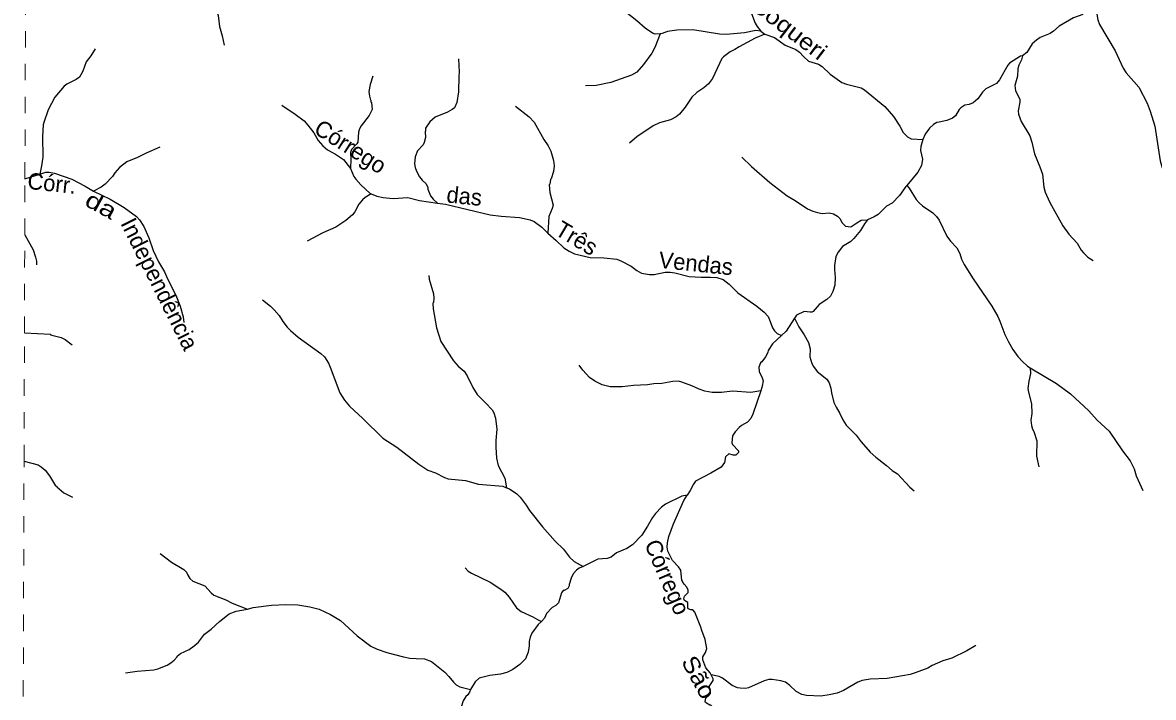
# Model space of a CAD drawing. Extents: x 551.6 to 577.6, y 7567 to 7594.7.
# Drawn here: x 551.65 to 558.55, y 7579.74 to 7583.85 of the extents above; entities that cross this region are included whole.
import ezdxf
from ezdxf.enums import TextEntityAlignment as Align

# ---------------------------------------------------------------- set-up
doc = ezdxf.new("R2010")
doc.units = 0
doc.header["$LTSCALE"] = 0.04
doc.linetypes.add('SHORT_DASHED', pattern=[2.7, 1.5, -1.2])
doc.layers.add('53', color=7, linetype='SHORT_DASHED', lineweight=13)
doc.layers.add('7', color=7, linetype='Continuous', lineweight=25)
doc.layers.add('61', color=7, linetype='Continuous')

msp = doc.modelspace()

# ---------------------------------------------------------------- linework, layer by layer
at = {"layer": '53'}
msp.add_lwpolyline([(551.6503, 7578.541), (551.6589, 7581.176), (551.6615, 7581.9586), (551.6634, 7582.5573), (551.6645, 7582.8996), (551.6852, 7589.2613), (551.6863, 7589.5882), (551.6896, 7590.6141), (551.6917, 7591.2598), (551.6958, 7592.5139), (551.6971, 7592.9033), (551.701, 7594.113), (551.703, 7594.7296), (552.7903, 7594.7256), (553.4424, 7594.7233), (554.6279, 7594.7189), (556.5859, 7594.7118), (557.3702, 7594.7089), (557.7663, 7594.7075), (559.9893, 7594.6994)], dxfattribs=at)
at = {"layer": '7'}
msp.add_line((551.6645, 7582.8996), (551.7544, 7582.9273), dxfattribs=at)
for points in [[(552.7391, 7584.4841), (552.7273, 7584.4326), (552.7273, 7584.3988), (552.7337, 7584.3763), (552.7466, 7584.3529), (552.7804, 7584.3232), (552.7933, 7584.2958), (552.7933, 7584.2507), (552.7691, 7584.1493), (552.7667, 7584.0962), (552.7836, 7584.0286), (552.7933, 7584.0061), (552.8222, 7583.9626), (552.8448, 7583.895), (552.8528, 7583.8274), (552.8689, 7583.7711), (552.8802, 7583.7139)], [(556.0535, 7584.2708), (556.0607, 7584.2547), (556.0656, 7584.1622), (556.0624, 7584.0761), (556.0591, 7584.0688), (556.064, 7584.0286), (556.0865, 7583.9739), (556.0897, 7583.9449), (556.0994, 7583.9063), (556.1211, 7583.8483), (556.134, 7583.8266), (556.1565, 7583.7992), (556.1801, 7583.78)], [(555.5411, 7583.7827), (555.5119, 7583.7815), (555.4942, 7583.7871), (555.4507, 7583.8169), (555.4, 7583.8628), (555.2455, 7583.9843), (555.2366, 7583.9948), (555.2238, 7584.0286), (555.2238, 7584.1187)], [(558.1211, 7583.8998), (558.0639, 7583.8813), (557.9778, 7583.829), (557.9424, 7583.7984), (557.9215, 7583.7847), (557.8619, 7583.7606), (557.8386, 7583.7445), (557.8128, 7583.7212), (557.779, 7583.6696), (557.7527, 7583.6485)], [(558.204, 7583.9281), (558.2128, 7583.8692), (558.224, 7583.8403), (558.319, 7583.6793), (558.3681, 7583.5731), (558.3858, 7583.5449), (558.4631, 7583.4572), (558.5138, 7583.3606), (558.5331, 7583.3123), (558.5613, 7583.2206), (558.5943, 7583.0081), (558.6063, 7582.9663), (558.6192, 7582.9373)], [(556.1565, 7583.7992), (556.1251, 7583.8024), (556.0559, 7583.7887), (555.9449, 7583.7783), (555.9046, 7583.7807), (555.7405, 7583.8081), (555.6439, 7583.8048), (555.5875, 7583.7968), (555.5537, 7583.7839), (555.5411, 7583.7827)], [(555.5411, 7583.7827), (555.5087, 7583.6986), (555.4909, 7583.6648), (555.4402, 7583.5956), (555.3984, 7583.5489), (555.367, 7583.5312), (555.2415, 7583.4869), (555.1513, 7583.4676), (555.0861, 7583.4652)], [(556.1801, 7583.78), (556.1211, 7583.7557), (556.0237, 7583.7042), (555.998, 7583.6873), (555.9682, 7583.6737), (555.9279, 7583.6423), (555.9191, 7583.6326), (555.8603, 7583.5111), (555.8362, 7583.4789), (555.8081, 7583.4531), (555.7654, 7583.4242), (555.7356, 7583.3968), (555.6954, 7583.3365), (555.66, 7583.2938), (555.639, 7583.2777), (555.6052, 7583.2592), (555.5376, 7583.2399), (555.499, 7583.2214), (555.3992, 7583.1538), (555.3549, 7583.1168)], [(556.1801, 7583.78), (556.2402, 7583.7598), (556.3054, 7583.7139), (556.369, 7583.6873), (556.3923, 7583.6705), (556.4173, 7583.6455)], [(552.0931, 7583.6914), (552.0665, 7583.6479), (552.0384, 7583.6117), (552.0174, 7583.5554), (551.9965, 7583.5191), (551.9764, 7583.5046), (551.9201, 7583.4765), (551.9031, 7583.4636), (551.8468, 7583.3976), (551.8066, 7583.3196), (551.7792, 7583.2431), (551.776, 7583.227), (551.7712, 7583.1562), (551.7728, 7583.0306), (551.7663, 7582.9775), (551.7544, 7582.9273)], [(554.3111, 7583.6302), (554.3159, 7583.5489), (554.3127, 7583.5248), (554.3103, 7583.4282), (554.3015, 7583.3638), (554.287, 7583.3324), (554.2725, 7583.3212), (554.2435, 7583.3059), (554.1679, 7583.2745), (554.1349, 7583.2471), (554.1099, 7583.2085), (554.1099, 7583.1916), (554.1067, 7583.186), (554.1099, 7583.1498), (554.1019, 7583.1192), (554.0946, 7583.1063), (554.0616, 7583.0693), (554.0455, 7583.0331), (554.0423, 7582.9904), (554.0455, 7582.9679), (554.0536, 7582.9453), (554.0721, 7582.9115), (554.0882, 7582.8906), (554.1139, 7582.8673), (554.1244, 7582.8455)], [(556.4173, 7583.6455), (556.4471, 7583.6157), (556.5074, 7583.5972), (556.53, 7583.5843), (556.5791, 7583.5368), (556.6499, 7583.4861), (556.6788, 7583.4757), (556.7682, 7583.4539), (556.7883, 7583.4411), (556.913, 7583.3389), (556.9653, 7583.2793), (557.0056, 7583.219), (557.0257, 7583.1819), (557.0523, 7583.1554), (557.074, 7583.1425), (557.1448, 7583.1388)], [(557.7527, 7583.6485), (557.7404, 7583.6471), (557.6736, 7583.6045), (557.6631, 7583.5924), (557.614, 7583.5023), (557.5947, 7583.4797), (557.5303, 7583.4467), (557.5102, 7583.4274), (557.4804, 7583.3871), (557.4523, 7583.3622), (557.4273, 7583.3525), (557.4016, 7583.3477), (557.3774, 7583.3324), (557.3677, 7583.322), (557.3452, 7583.2825), (557.3259, 7583.268), (557.2921, 7583.2543), (557.2438, 7583.2447)], [(557.7527, 7583.6485), (557.7476, 7583.6246), (557.7315, 7583.5908), (557.7251, 7583.5699), (557.7235, 7583.5248), (557.7074, 7583.4685), (557.7106, 7583.4347), (557.7363, 7583.3847), (557.7363, 7583.367), (557.7267, 7583.3139), (557.7283, 7583.293), (557.746, 7583.2479), (557.7975, 7583.161), (557.8104, 7583.1224), (557.8257, 7583.0516), (557.8595, 7582.9727), (557.8748, 7582.9276), (557.8844, 7582.8471), (557.8917, 7582.8182), (557.9005, 7582.7989)], [(553.7872, 7583.5256), (553.7719, 7583.4749), (553.7638, 7583.4314), (553.7671, 7583.4025), (553.7735, 7583.3791), (553.7767, 7583.3775), (553.7767, 7583.367), (553.7807, 7583.3638), (553.784, 7583.322), (553.7646, 7583.2858), (553.7164, 7583.2222), (553.7059, 7583.2029), (553.6995, 7583.1836), (553.6954, 7583.1224), (553.6898, 7583.1111), (553.6576, 7583.0781), (553.6514, 7583.0591), (553.6536, 7583.0182), (553.6512, 7582.9613)], [(553.2335, 7583.3485), (553.3148, 7583.293), (553.3679, 7583.252), (553.392, 7583.2262), (553.4282, 7583.1787), (553.454, 7583.132), (553.483, 7583.0998), (553.5119, 7583.0765), (553.5611, 7583.0491), (553.6085, 7583.0169), (553.6512, 7582.9613)], [(554.6596, 7583.3421), (554.7417, 7583.2777), (554.7731, 7583.2447), (554.8326, 7583.1385), (554.8576, 7583.0999), (554.8737, 7583.0677), (554.8906, 7583.0113), (554.8954, 7582.9775), (554.8914, 7582.9437), (554.8761, 7582.8995), (554.8721, 7582.8954), (554.868, 7582.8665), (554.8648, 7582.8616), (554.868, 7582.815), (554.8882, 7582.7377), (554.8833, 7582.7168), (554.8632, 7582.6685), (554.8571, 7582.5664)], [(557.2438, 7583.2447), (557.2309, 7583.2415), (557.21, 7583.2302), (557.1867, 7583.2085), (557.1601, 7583.1707), (557.1448, 7583.1388)], [(557.1448, 7583.1388), (557.1327, 7583.0966), (557.1311, 7583.0709), (557.1432, 7583.0194), (557.136, 7582.9807), (557.115, 7582.9397), (557.0477, 7582.8573)], [(552.4883, 7583.091), (552.4045, 7583.0548), (552.3522, 7583.0282), (552.2862, 7583.0025), (552.2412, 7582.967), (552.2138, 7582.9357), (552.1985, 7582.9131), (552.1551, 7582.8656), (552.1301, 7582.8479), (552.0826, 7582.8242)], [(556.0406, 7583.0298), (556.0986, 7582.9735), (556.2112, 7582.8753), (556.3167, 7582.7948), (556.3666, 7582.7658), (556.4406, 7582.716), (556.4728, 7582.7007), (556.5018, 7582.6926), (556.5308, 7582.6878), (556.5742, 7582.691), (556.6, 7582.6846), (556.6241, 7582.6709), (556.6402, 7582.6556), (556.6498, 7582.6322), (556.674, 7582.6097), (556.7046, 7582.6057), (556.7424, 7582.6306)], [(551.7544, 7582.9273), (551.7921, 7582.9389), (551.8114, 7582.9389), (551.8452, 7582.9332), (551.9498, 7582.8962), (552.0319, 7582.8544), (552.0826, 7582.8242)], [(553.6512, 7582.9613), (553.6729, 7582.9131), (553.685, 7582.897), (553.7155, 7582.8616), (553.7719, 7582.8101), (553.7783, 7582.8074)], [(554.1244, 7582.8455), (554.1244, 7582.8359), (554.1405, 7582.7956), (554.1558, 7582.7755), (554.1832, 7582.7497)], [(557.0477, 7582.8573), (557.041, 7582.8528), (557.0032, 7582.7972), (556.9589, 7582.7506), (556.9235, 7582.732), (556.872, 7582.6805), (556.8479, 7582.666), (556.8079, 7582.6495)], [(557.0477, 7582.8573), (557.0611, 7582.8423), (557.1046, 7582.7723), (557.1223, 7582.753), (557.144, 7582.7337), (557.2052, 7582.691), (557.2293, 7582.6693), (557.2454, 7582.6476), (557.2921, 7582.5494), (557.3146, 7582.5188), (557.3524, 7582.4769), (557.3701, 7582.4431), (557.3814, 7582.4093), (557.3975, 7582.3771), (557.4514, 7582.2886), (557.5657, 7582.1212), (557.6019, 7582.0601), (557.6156, 7582.0311), (557.6454, 7581.949), (557.6671, 7581.9039), (557.6945, 7581.8589), (557.7259, 7581.8154)], [(552.0826, 7582.8242), (552.184, 7582.7739), (552.2693, 7582.7248), (552.3458, 7582.6693), (552.3635, 7582.6492), (552.3908, 7582.6089), (552.4206, 7582.5397), (552.4472, 7582.4608), (552.4794, 7582.3932), (552.5164, 7582.3321), (552.5293, 7582.3031)], [(553.7783, 7582.8074), (553.7421, 7582.7852), (553.7244, 7582.7699), (553.7035, 7582.7449), (553.6777, 7582.6974), (553.6633, 7582.6789), (553.6238, 7582.6443), (553.5627, 7582.6049), (553.4822, 7582.5703), (553.388, 7582.518)], [(553.7783, 7582.8074), (553.8122, 7582.7932), (553.8508, 7582.7844), (553.9119, 7582.7795), (554.0013, 7582.7844)], [(554.0013, 7582.7844), (554.0729, 7582.7666), (554.1832, 7582.7497)], [(557.9005, 7582.7989), (557.9198, 7582.7538), (557.9987, 7582.6121), (558.0357, 7582.5606), (558.0872, 7582.5059), (558.1122, 7582.464), (558.1259, 7582.4472), (558.1516, 7582.4214), (558.1846, 7582.3997)], [(554.1832, 7582.7497), (554.2323, 7582.7449), (554.5043, 7582.6781), (554.5719, 7582.6701), (554.6829, 7582.6636), (554.7489, 7582.6491), (554.7731, 7582.6387), (554.8198, 7582.6049), (554.8571, 7582.5664), (554.9067, 7582.5236)], [(556.8079, 7582.6495), (556.7883, 7582.625), (556.7641, 7582.584), (556.7247, 7582.5349), (556.7046, 7582.5164), (556.6547, 7582.485), (556.6273, 7582.4512), (556.6144, 7582.4254), (556.6064, 7582.3707), (556.6064, 7582.345)], [(556.7424, 7582.6306), (556.769, 7582.6459), (556.8079, 7582.6495)], [(551.6634, 7582.5573), (551.7156, 7582.4657), (551.7293, 7582.4206), (551.7341, 7582.3965), (551.7342, 7582.3747)], [(554.9067, 7582.5236), (554.9533, 7582.4785), (554.9872, 7582.4568), (555.0194, 7582.4423), (555.1143, 7582.4198), (555.198, 7582.4174), (555.2769, 7582.4085), (555.3059, 7582.3972), (555.3638, 7582.3667), (555.3992, 7582.3393), (555.4282, 7582.324), (555.4765, 7582.316), (555.5055, 7582.316), (555.5731, 7582.3304), (555.602, 7582.3304), (555.631, 7582.3256), (555.7179, 7582.3023), (555.792, 7582.2991)], [(552.5293, 7582.3031), (552.5888, 7582.1791), (552.6114, 7582.1228), (552.6307, 7582.0568), (552.6339, 7582.0222)], [(554.1292, 7582.3087), (554.1316, 7582.287), (554.1574, 7582.1969), (554.1598, 7582.1711), (554.1582, 7582.1454), (554.155, 7582.1405), (554.1566, 7582.1067), (554.1775, 7581.9908), (554.2033, 7581.9071), (554.2805, 7581.7888), (554.3095, 7581.7566), (554.3449, 7581.726), (554.3642, 7581.6979), (554.3988, 7581.6255), (554.4238, 7581.5844), (554.4785, 7581.5313)], [(555.792, 7582.2991), (555.8483, 7582.2999), (555.8869, 7582.2966), (555.9256, 7582.2838), (555.9626, 7582.2556), (556.0165, 7582.2041), (556.1316, 7582.1228), (556.1775, 7582.085), (556.2, 7582.0584), (556.2137, 7582.0295), (556.2265, 7581.9908), (556.2402, 7581.9715), (556.2555, 7581.9554), (556.2814, 7581.9441)], [(556.6064, 7582.345), (556.6096, 7582.2967), (556.608, 7582.25), (556.5967, 7582.2114), (556.5806, 7582.1832), (556.5597, 7582.1638), (556.5114, 7582.1333), (556.476, 7582.0898), (556.4672, 7582.085), (556.4583, 7582.085), (556.4205, 7582.0906), (556.373, 7582.0673), (556.3608, 7582.0482)], [(553.1144, 7582.1598), (553.1627, 7582.1228), (553.186, 7582.1003), (553.2158, 7582.0649), (553.2391, 7582.0279), (553.2657, 7581.994), (553.2858, 7581.9739), (553.3325, 7581.9337), (553.4701, 7581.8339), (553.4934, 7581.8122), (553.5168, 7581.7752), (553.528, 7581.751), (553.5868, 7581.5933), (553.6158, 7581.5482), (553.6463, 7581.512), (553.7276, 7581.4371), (553.85, 7581.3172), (553.9345, 7581.2617), (554.0681, 7581.1578)], [(556.3608, 7582.0482), (556.3102, 7581.9691), (556.2814, 7581.9441)], [(556.3608, 7582.0482), (556.3891, 7581.9957), (556.4213, 7581.9474), (556.447, 7581.9007), (556.4567, 7581.8621), (556.4559, 7581.8122), (556.468, 7581.7735), (556.4784, 7581.7542), (556.501, 7581.7244), (556.5597, 7581.677), (556.5734, 7581.6544), (556.5839, 7581.6222), (556.5871, 7581.5933), (556.6016, 7581.5353), (556.6152, 7581.5064), (556.6394, 7581.4677), (556.6563, 7581.4291), (556.6764, 7581.3969), (556.7384, 7581.3357), (556.7682, 7581.2955), (556.8245, 7581.2327), (556.8591, 7581.2005), (556.9243, 7581.1514)], [(551.6615, 7581.9586), (551.8211, 7581.9506), (551.8214, 7581.947), (551.8862, 7581.9313), (551.9096, 7581.9184), (551.9523, 7581.8854)], [(556.2814, 7581.9441), (556.2265, 7581.8927), (556.2016, 7581.8524), (556.1984, 7581.8395), (556.1847, 7581.8138), (556.1614, 7581.7824), (556.1533, 7581.7768), (556.1444, 7581.7494), (556.146, 7581.7236), (556.1646, 7581.685), (556.1702, 7581.6665), (556.1654, 7581.6335), (556.1564, 7581.6066)], [(557.7259, 7581.8154), (557.7532, 7581.784), (557.783, 7581.7558), (557.8007, 7581.7453)], [(556.1564, 7581.6066), (556.0946, 7581.5965), (555.9835, 7581.6045), (555.9159, 7581.5965), (555.8596, 7581.5949), (555.8145, 7581.6045), (555.7807, 7581.6158), (555.7356, 7581.6367), (555.6745, 7581.6592), (555.6535, 7581.6641), (555.6197, 7581.6625), (555.5521, 7581.6512), (555.5022, 7581.648), (555.4636, 7581.6415), (555.3783, 7581.6383), (555.3107, 7581.6303), (555.2366, 7581.6303), (555.1884, 7581.6415), (555.1433, 7581.6641), (555.1095, 7581.6874), (555.0692, 7581.7309), (555.0483, 7581.7615)], [(557.8007, 7581.7453), (557.8031, 7581.7108), (557.7919, 7581.6657), (557.7862, 7581.6206), (557.7895, 7581.5981), (557.8088, 7581.5257), (557.8104, 7581.4677), (557.8048, 7581.4275), (557.808, 7581.3937), (557.8144, 7581.3711), (557.8233, 7581.3574), (557.8402, 7581.3019), (557.8394, 7581.207), (557.8539, 7581.1418)], [(557.8007, 7581.7453), (557.9601, 7581.6504), (558.047, 7581.5876), (558.1589, 7581.4838), (558.2088, 7581.4275), (558.282, 7581.3591), (558.3633, 7581.2408), (558.4108, 7581.1796), (558.4349, 7581.1305), (558.4478, 7581.0879), (558.4888, 7580.9985)], [(556.1564, 7581.6066), (556.1082, 7581.4629), (556.0953, 7581.4371), (556.0744, 7581.4146)], [(554.4785, 7581.5313), (554.5163, 7581.4894), (554.526, 7581.4717), (554.5365, 7581.4387), (554.5445, 7581.3711), (554.5381, 7581.3035), (554.5378, 7581.2614), (554.5429, 7581.1957), (554.5533, 7581.1506), (554.5928, 7581.0734), (554.6048, 7581.0152)], [(556.0744, 7581.4146), (556.0382, 7581.3945), (556.0237, 7581.3816), (556.0004, 7581.3567), (555.9843, 7581.3309), (555.9795, 7581.2882), (555.9835, 7581.2786), (556.0205, 7581.2408), (556.0205, 7581.2295), (556.0036, 7581.2142), (555.9867, 7581.2134), (555.961, 7581.2214), (555.9416, 7581.2037), (555.9352, 7581.1683), (555.9135, 7581.1401), (555.8515, 7581.1039), (555.7573, 7581.0549), (555.7445, 7581.0363), (555.7259, 7580.9977), (555.7067, 7580.9695)], [(551.6589, 7581.176), (551.7454, 7581.1538), (551.7639, 7581.1434), (551.7881, 7581.1217), (551.8146, 7581.0879), (551.8509, 7581.0267), (551.8597, 7581.0235), (551.8597, 7581.0202), (551.9016, 7580.984), (551.9547, 7580.9567)], [(554.0681, 7581.1578), (554.1244, 7581.1216), (554.1695, 7581.1063), (554.2258, 7581.0774), (554.2484, 7581.0701), (554.3546, 7581.0589), (554.4335, 7581.0363), (554.5815, 7581.0235), (554.6048, 7581.0152)], [(556.9243, 7581.1514), (556.9589, 7581.12), (556.9903, 7581.0999), (557.0659, 7581.0186), (557.0925, 7580.9969)], [(554.6048, 7581.0152), (554.6218, 7581.009), (554.6669, 7580.9784), (554.687, 7580.9583), (554.724, 7580.9092), (554.7449, 7580.8754), (554.823, 7580.7772), (554.9002, 7580.6887), (554.9517, 7580.6404), (554.9879, 7580.5913), (555.0169, 7580.5647), (555.0716, 7580.5337)], [(555.7067, 7580.9695), (555.6745, 7580.9639), (555.5747, 7580.9148), (555.5497, 7580.8963), (555.5143, 7580.8585)], [(555.7952, 7580.1446), (555.7903, 7580.1639), (555.7541, 7580.2557), (555.7421, 7580.2694), (555.7292, 7580.2702), (555.7131, 7580.2774), (555.7099, 7580.283), (555.7114, 7580.316), (555.6905, 7580.3265), (555.6857, 7580.337), (555.6905, 7580.3547), (555.7131, 7580.3764), (555.7131, 7580.3893), (555.705, 7580.4086), (555.6873, 7580.4263), (555.6777, 7580.4424), (555.6777, 7580.4472), (555.6744, 7580.4488), (555.668, 7580.5116), (555.6535, 7580.5325), (555.6165, 7580.572), (555.5891, 7580.6275), (555.5843, 7580.6533), (555.5859, 7580.679), (555.5956, 7580.7176), (555.6229, 7580.7949), (555.6865, 7580.9366), (555.7067, 7580.9695)], [(555.5143, 7580.8585), (555.4942, 7580.8335), (555.4652, 7580.7804), (555.4298, 7580.7265), (555.3735, 7580.6677), (555.3381, 7580.6452), (555.2745, 7580.6178), (555.2431, 7580.5921), (555.2173, 7580.5832), (555.161, 7580.58), (555.0716, 7580.5337)], [(552.4899, 7580.6146), (552.5583, 7580.5607), (552.6347, 7580.5164), (552.65, 7580.5003), (552.6581, 7580.481), (552.6717, 7580.4617), (552.6886, 7580.4456), (552.7627, 7580.4158), (552.8013, 7580.3732), (552.8174, 7580.3603), (552.8915, 7580.3305), (552.9285, 7580.3104), (553.0235, 7580.2742)], [(554.3514, 7580.5269), (554.3707, 7580.5068), (554.39, 7580.4947), (554.5043, 7580.4384), (554.5695, 7580.3973), (554.5936, 7580.378), (554.621, 7580.3474), (554.6644, 7580.283), (554.6934, 7580.2597), (554.765, 7580.2275), (554.7924, 7580.2106), (554.8168, 7580.2001)], [(555.0716, 7580.5337), (555.0467, 7580.5237), (555.0314, 7580.5132), (555.0113, 7580.4891), (554.9984, 7580.4633), (554.9855, 7580.4247), (554.9855, 7580.4167), (554.9775, 7580.4005), (554.9566, 7580.3885), (554.9501, 7580.3885), (554.9397, 7580.3732), (554.9203, 7580.3136), (554.9043, 7580.2967), (554.8833, 7580.2838), (554.8471, 7580.2484), (554.835, 7580.2195), (554.8168, 7580.2001)], [(553.0235, 7580.2742), (553.0573, 7580.2838), (553.1699, 7580.2991)], [(553.1699, 7580.2991), (553.2568, 7580.3024), (553.3293, 7580.3007), (553.4033, 7580.2895), (553.4613, 7580.2742), (553.5305, 7580.2428), (553.59, 7580.205), (553.693, 7580.1124), (553.7767, 7580.0488), (553.8154, 7580.0303), (553.8733, 7580.0094), (553.9747, 7579.9829), (554.0134, 7579.9764), (554.052, 7579.974)], [(552.2774, 7579.8871), (552.349, 7579.8967), (552.452, 7579.9048), (552.4762, 7579.9112), (552.5325, 7579.9338), (552.5551, 7579.9466), (552.5744, 7579.9627), (552.5937, 7579.9837), (552.5945, 7579.9885), (552.6146, 7580.0038), (552.6661, 7580.0287), (552.6975, 7580.0505), (552.7232, 7580.073), (552.7603, 7580.1213), (552.8021, 7580.1519), (552.852, 7580.1993), (552.9108, 7580.2452), (552.9542, 7580.2629), (553.0235, 7580.2742)], [(554.8168, 7580.2001), (554.798, 7580.18), (554.7594, 7580.1285), (554.7481, 7580.1028), (554.7425, 7580.077)], [(555.8528, 7579.8734), (555.8467, 7579.8855), (555.8209, 7579.9161), (555.8016, 7579.966), (555.8016, 7579.9837), (555.8193, 7580.011), (555.8257, 7580.0336), (555.8161, 7580.0899), (555.7952, 7580.1446)], [(554.7425, 7580.077), (554.7425, 7580.0513), (554.7352, 7580.0126), (554.72, 7579.9716), (554.6862, 7579.9378), (554.6427, 7579.9064), (554.6057, 7579.8887), (554.5671, 7579.8782), (554.5027, 7579.8702), (554.4367, 7579.8533), (554.4117, 7579.8308), (554.3837, 7579.7851)], [(557.4684, 7580.0537), (557.4128, 7580.0199), (557.3211, 7579.9764), (557.2664, 7579.9595), (557.2012, 7579.9305), (557.1762, 7579.9152), (557.099, 7579.8871), (557.0668, 7579.8766), (556.9267, 7579.8509), (556.8237, 7579.8468), (556.7754, 7579.8388), (556.7489, 7579.8291), (556.6611, 7579.7784), (556.6225, 7579.7631), (556.5742, 7579.7511)], [(554.052, 7579.974), (554.1035, 7579.9716), (554.1453, 7579.9555), (554.2266, 7579.8895), (554.2524, 7579.8637), (554.2797, 7579.8283), (554.2974, 7579.8122), (554.3192, 7579.801), (554.3837, 7579.7851)], [(555.9119, 7579.5547), (555.8885, 7579.5627), (555.8837, 7579.5764), (555.8877, 7579.6038), (555.8845, 7579.6127), (555.8579, 7579.6215), (555.8563, 7579.6271), (555.8692, 7579.665), (555.8644, 7579.6746), (555.8507, 7579.6883), (555.8458, 7579.6883), (555.8193, 7579.7044), (555.8169, 7579.7116), (555.8201, 7579.7326), (555.8386, 7579.747), (555.8483, 7579.7599), (555.8491, 7579.78), (555.8418, 7579.8034), (555.8644, 7579.8404), (555.8644, 7579.8501), (555.8528, 7579.8734)], [(556.5742, 7579.7511), (556.5227, 7579.743), (556.4358, 7579.7487), (556.4068, 7579.7535), (556.3714, 7579.7728), (556.3336, 7579.8098), (556.3062, 7579.8291), (556.2781, 7579.838), (556.2249, 7579.8452), (556.2056, 7579.8452), (556.1767, 7579.838), (556.0801, 7579.7937), (556.0624, 7579.7905), (556.0302, 7579.7921), (556.0141, 7579.7953), (555.9811, 7579.8098), (555.9223, 7579.8541), (555.9022, 7579.8645), (555.8528, 7579.8734)], [(554.3837, 7579.7851), (554.3771, 7579.768), (554.3674, 7579.7527), (554.3562, 7579.7422), (554.3401, 7579.7149), (554.3272, 7579.6762), (554.3103, 7579.6529), (554.2821, 7579.6247), (554.2805, 7579.6127), (554.2773, 7579.6102), (554.2773, 7579.5869), (554.287, 7579.5628), (554.291, 7579.5595), (554.2918, 7579.5507), (554.2818, 7579.4878)]]:
    msp.add_lwpolyline(points, dxfattribs=at)

# ---------------------------------------------------------------- texts
at = {"layer": '61'}
for s, rotation, width, p in [('Coqueri', 322.641, 1.15, (556.2965, 7583.7795)), ('da', 331.141, 1.3, (552.106, 7582.6941)), ('São', 298.628, 1.15, (555.7331, 7579.8357))]:
    msp.add_text(s, height=0.1, rotation=rotation, dxfattribs=dict(at, width=width)).set_placement(p, align=Align.CENTER)
for s, rotation, p in [('Córrego', 327.708, (553.6248, 7583.0528)), ('Córr.', 353.804, (551.8238, 7582.822)), ('das', 354.209, (554.3415, 7582.7441)), ('Independência', 296.577, (552.4415, 7582.2354)), ('Três', 329.227, (555.0071, 7582.4942)), ('Vendas', 354.209, (555.7547, 7582.3334)), ('Córrego', 293.387, (555.5394, 7580.4503))]:
    msp.add_text(s, height=0.1, rotation=rotation, dxfattribs=at).set_placement(p, align=Align.CENTER)

doc.saveas('drawing.dxf')
